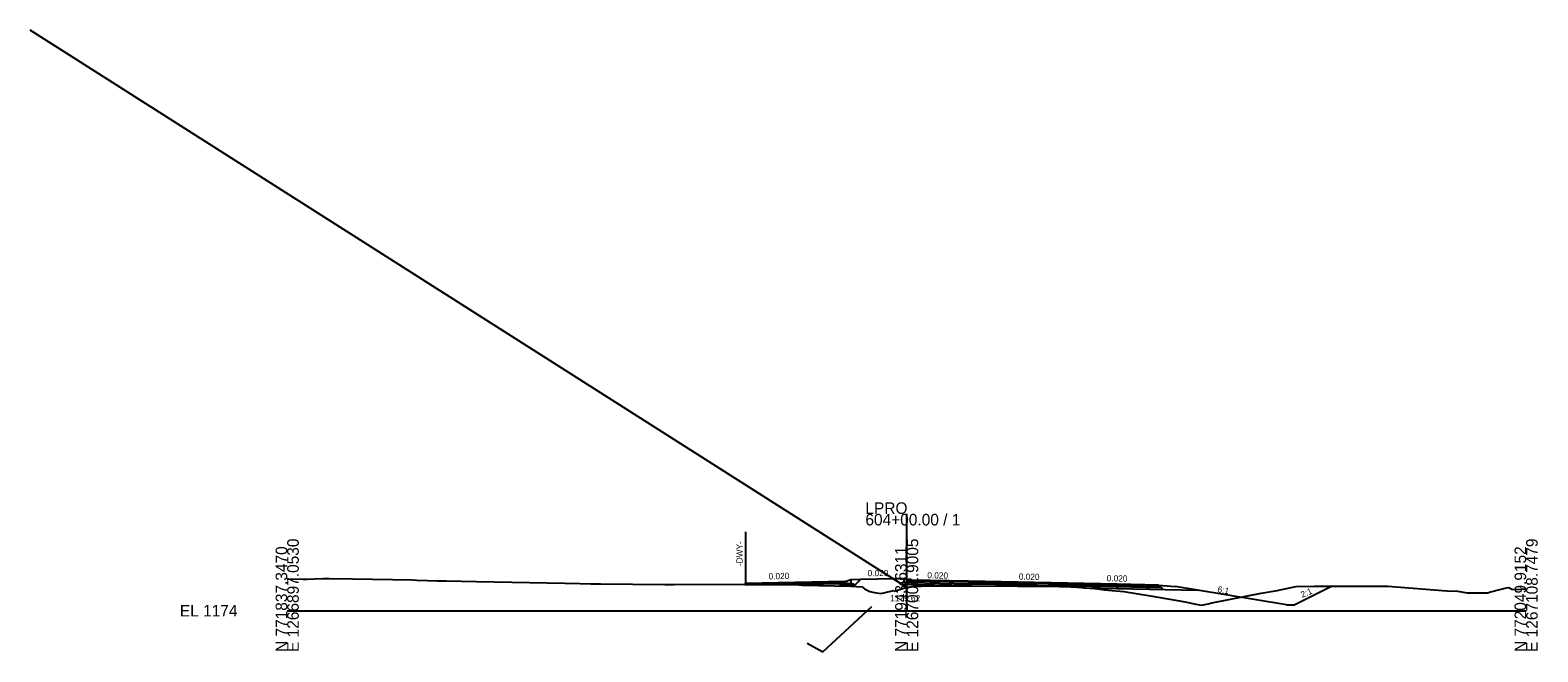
# Model space of a CAD drawing. Extents: x -3833 to 1267678, y -522 to 773248.
# Drawn here: x 937.8 to 1302.8, y 4990 to 5140.7 of the extents above; entities that cross this region are included whole.
import ezdxf

# ---------------------------------------------------------------- set-up
doc = ezdxf.new("R2010")
doc.units = 0
for name, color, linetype in [('Exist Cross Section Cell', 7, 'Continuous'), ('Exist XS Center Line Elevation Label', 7, 'Continuous'), ('Exist XS Ground Line', 7, 'Continuous'), ('Prop CMT DNC', 7, 'Continuous'), ('Prop CMT Pvmt Course 1', 7, 'Continuous'), ('Prop CMT Pvmt Course 2', 7, 'Continuous'), ('Prop CMT Pvmt Course 3', 7, 'Continuous'), ('Prop CMT Pvmt Course 4', 7, 'Continuous'), ('Prop CMT Shld Paved Course 1', 7, 'Continuous'), ('Prop CMT Shld Paved Course 2', 7, 'Continuous'), ('Prop CMT Shld Paved Course 4', 7, 'Continuous'), ('Prop CMT Slope Grass', 7, 'Continuous'), ('Prop CMT Subgrade Earthwork', 7, 'Continuous'), ('Prop Conc Curb and Gutter', 7, 'Continuous'), ('Prop Conc Island Cover', 7, 'Continuous'), ('Prop Corridor Mesh Bottom', 7, 'Continuous'), ('Prop XS Ditch Slope Text', 7, 'Continuous'), ('Prop XS Finish Grade', 7, 'Continuous'), ('Prop XS SE Text', 7, 'Continuous'), ('Prop XS Shear Point Element', 7, 'Continuous'), ('Prop XS Shear Point Label', 7, 'Continuous'), ('Scratch_Level_1', 7, 'Continuous'), ('Scratch_Level_5', 7, 'Continuous')]:
    doc.layers.add(name, color=color, linetype=linetype)

msp = doc.modelspace()

# ---------------------------------------------------------------- linework, layer by layer
at = {"layer": 'Exist Cross Section Cell'}
for p, q in [((1150, 5000), (1150, 5023.46)), ((1000, 5000), (1150, 5000)), ((1150, 5000), (1300, 5000))]:
    msp.add_line(p, q, dxfattribs=at)
at = {"layer": 'Exist XS Ground Line'}
for p, q in [((1000, 5007.74), (1003.75, 5007.64)), ((1003.75, 5007.64), (1004.71, 5007.66)), ((1004.71, 5007.66), (1006.59, 5007.7)), ((1006.59, 5007.7), (1008.72, 5007.77)), ((1008.72, 5007.77), (1010.14, 5007.82)), ((1010.14, 5007.82), (1015.79, 5007.73)), ((1015.79, 5007.73), (1030.31, 5007.48)), ((1030.31, 5007.48), (1031.37, 5007.43)), ((1031.37, 5007.43), (1034, 5007.34)), ((1034, 5007.34), (1036.29, 5007.26)), ((1036.29, 5007.26), (1038.5, 5007.2)), ((1038.5, 5007.2), (1045.86, 5007.04)), ((1045.86, 5007.04), (1067.25, 5006.66)), ((1067.25, 5006.66), (1070.89, 5006.57)), ((1070.89, 5006.57), (1073.51, 5006.54)), ((1073.51, 5006.54), (1075.9, 5006.51)), ((1075.9, 5006.51), (1091.41, 5006.37)), ((1091.41, 5006.37), (1092.62, 5006.36)), ((1092.62, 5006.36), (1093.73, 5006.35)), ((1093.73, 5006.35), (1109.86, 5006.4)), ((1109.86, 5006.4), (1110.85, 5006.39)), ((1110.85, 5006.39), (1111.66, 5006.39)), ((1111.66, 5006.39), (1112.36, 5006.38)), ((1112.36, 5006.38), (1123.85, 5006.24)), ((1123.85, 5006.24), (1124.71, 5006.22)), ((1124.71, 5006.22), (1136.51, 5005.92)), ((1136.51, 5005.92), (1139.26, 5005.78)), ((1139.26, 5005.78), (1139.8, 5005.29)), ((1146.97, 5004.7), (1149.35, 5005.48)), ((1149.35, 5005.48), (1150, 5005.62)), ((1150, 5005.62), (1150.37, 5005.69)), ((1150.37, 5005.69), (1151.55, 5005.93)), ((1151.55, 5005.93), (1153.6, 5005.98)), ((1153.6, 5005.98), (1160.64, 5006.02)), ((1160.64, 5006.02), (1165.83, 5006.05)), ((1165.83, 5006.05), (1176.95, 5005.96)), ((1176.95, 5005.96), (1178.3, 5005.94)), ((1178.3, 5005.94), (1181.63, 5005.91)), ((1181.63, 5005.91), (1187.02, 5005.84)), ((1187.02, 5005.84), (1189.65, 5005.81)), ((1189.65, 5005.81), (1190.26, 5005.76)), ((1190.26, 5005.76), (1195.46, 5005.35)), ((1239.71, 5004.9), (1244.22, 5005.84)), ((1244.22, 5005.84), (1248.79, 5005.92)), ((1248.79, 5005.92), (1266.54, 5005.92)), ((1266.54, 5005.92), (1280.84, 5004.82)), ((1293.94, 5005.2), (1295.28, 5005.55)), ((1295.28, 5005.55), (1295.83, 5005.66)), ((1295.83, 5005.66), (1296.56, 5005.18)), ((1139.8, 5005.29), (1141.09, 5004.67)), ((1141.09, 5004.67), (1142.22, 5004.43)), ((1142.22, 5004.43), (1143.71, 5004.19)), ((1143.71, 5004.19), (1146.2, 5004.73)), ((1146.2, 5004.73), (1146.95, 5004.86)), ((1146.95, 5004.86), (1146.97, 5004.7)), ((1195.46, 5005.35), (1196.19, 5005.27)), ((1196.19, 5005.27), (1197.9, 5005.09)), ((1197.9, 5005.09), (1201.6, 5004.75)), ((1201.6, 5004.75), (1202.62, 5004.62)), ((1202.62, 5004.62), (1209.04, 5003.6)), ((1209.04, 5003.6), (1217.43, 5002.17)), ((1217.43, 5002.17), (1218.17, 5002)), ((1218.17, 5002), (1220.01, 5001.62)), ((1222.98, 5001.68), (1223.92, 5001.93)), ((1223.92, 5001.93), (1235.82, 5004.28)), ((1235.82, 5004.28), (1239.71, 5004.9)), ((1280.84, 5004.82), (1283.36, 5004.7)), ((1283.36, 5004.7), (1285.74, 5004.34)), ((1285.74, 5004.34), (1286.6, 5004.34)), ((1286.6, 5004.34), (1290.73, 5004.33)), ((1290.73, 5004.33), (1291.16, 5004.52)), ((1291.16, 5004.52), (1293.94, 5005.2)), ((1296.56, 5005.18), (1297.34, 5005.12)), ((1297.34, 5005.12), (1300, 5005.28)), ((1220.01, 5001.62), (1221.39, 5001.33)), ((1221.39, 5001.33), (1222.98, 5001.68))]:
    msp.add_line(p, q, dxfattribs=at)
at = {"layer": 'Prop CMT Pvmt Course 1'}
for p, q in [((1111, 5006.66), (1135, 5007.14)), ((1111, 5006.41), (1111, 5006.66)), ((1111, 5006.66), (1111, 5006.66)), ((1135, 5007.14), (1135, 5007.14)), ((1135, 5007.14), (1135, 5007.14)), ((1135, 5007.14), (1135, 5006.89)), ((1135, 5006.89), (1135, 5006.89)), ((1201, 5006.42), (1165, 5007.14)), ((1165, 5007.14), (1165, 5007.14)), ((1165, 5007.14), (1165, 5007.14)), ((1165, 5007.14), (1165, 5006.89)), ((1165, 5006.89), (1165, 5006.89)), ((1201, 5006.42), (1195, 5006.54)), ((1195, 5006.29), (1195, 5006.54)), ((1195, 5006.54), (1195, 5006.54)), ((1195, 5006.54), (1195, 5006.54)), ((1195, 5006.54), (1201, 5006.42)), ((1195, 5006.29), (1201, 5006.17)), ((1201, 5006.17), (1201, 5006.42))]:
    msp.add_line(p, q, dxfattribs=at)
at = {"layer": 'Prop CMT Pvmt Course 2'}
for p, q in [((1135, 5006.89), (1135, 5006.89)), ((1135, 5006.89), (1135, 5006.56)), ((1135, 5006.56), (1135, 5006.55)), ((1150, 5007.19), (1150, 5007.19)), ((1150, 5007.19), (1150, 5007.19)), ((1150, 5006.86), (1150, 5006.86)), ((1150, 5006.86), (1150, 5006.86)), ((1165, 5006.89), (1150.94, 5007.17)), ((1150.94, 5006.84), (1165, 5006.55)), ((1165, 5006.89), (1165, 5006.89)), ((1165, 5006.55), (1165, 5006.55)), ((1195, 5005.96), (1201, 5005.84))]:
    msp.add_line(p, q, dxfattribs=at)
at = {"layer": 'Prop CMT Pvmt Course 3'}
for p, q in [((1135, 5006.55), (1137.01, 5006.6)), ((1135, 5006.55), (1135, 5006.55)), ((1137.01, 5006.6), (1137.01, 5006.6)), ((1137.01, 5006.6), (1137.01, 5006.6)), ((1137.01, 5006.6), (1137.46, 5006.15)), ((1137.3, 5006.31), (1137.3, 5006.31)), ((1148.48, 5006.43), (1148.93, 5006.88)), ((1148.93, 5006.88), (1149.43, 5006.87))]:
    msp.add_line(p, q, dxfattribs=at)
at = {"layer": 'Prop CMT Pvmt Course 4'}
for p, q in [((1134, 5005.98), (1134, 5007.12)), ((1137.46, 5006.15), (1134, 5006.08)), ((1135, 5006.56), (1135, 5006.56)), ((1135, 5006.56), (1135, 5006.55)), ((1138.29, 5005.83), (1138.29, 5005.83)), ((1150, 5006.86), (1150, 5006.86)), ((1150, 5006.86), (1150, 5006.86)), ((1165, 5006.55), (1165, 5006.55)), ((1165, 5006.55), (1165, 5006.55)), ((1165, 5006.55), (1165, 5006.05)), ((1195, 5005.96), (1195, 5005.5)), ((1201, 5005.84), (1195, 5005.96)), ((1195, 5005.5), (1201, 5005.38))]:
    msp.add_line(p, q, dxfattribs=at)
at = {"layer": 'Prop CMT Shld Paved Course 1'}
for p, q in [((1135, 5007.14), (1135, 5007.14)), ((1135, 5007.14), (1135, 5006.89)), ((1150, 5007.44), (1150, 5007.44)), ((1150, 5007.44), (1150, 5007.44)), ((1150, 5007.19), (1150, 5007.19)), ((1150, 5007.19), (1150, 5007.19)), ((1165, 5007.14), (1150.94, 5007.42)), ((1165, 5006.89), (1165, 5007.14)), ((1165, 5007.14), (1165, 5007.14)), ((1201, 5006.42), (1201, 5006.17)), ((1211, 5006.22), (1201, 5006.42)), ((1201, 5006.17), (1211.26, 5005.96)), ((1211.26, 5005.96), (1211, 5006.22))]:
    msp.add_line(p, q, dxfattribs=at)
at = {"layer": 'Prop CMT Shld Paved Course 2'}
for p, q in [((1111, 5006.41), (1111.66, 5006.42)), ((1111, 5006.39), (1111, 5006.41)), ((1111.66, 5006.42), (1112.36, 5006.44)), ((1111.66, 5006.42), (1111.66, 5006.42)), ((1111.66, 5006.39), (1111.66, 5006.39)), ((1112.36, 5006.44), (1123.85, 5006.66)), ((1112.36, 5006.44), (1112.36, 5006.44)), ((1112.36, 5006.38), (1112.36, 5006.38)), ((1123.85, 5006.33), (1121.08, 5006.28)), ((1121.08, 5006.28), (1121.08, 5006.28)), ((1123.85, 5006.66), (1124.71, 5006.68)), ((1123.85, 5006.66), (1123.85, 5006.66)), ((1124.71, 5006.35), (1123.85, 5006.33)), ((1123.85, 5006.33), (1123.85, 5006.33)), ((1124.71, 5006.68), (1135, 5006.89)), ((1124.71, 5006.68), (1124.71, 5006.68)), ((1135, 5006.55), (1124.71, 5006.35)), ((1124.71, 5006.35), (1124.71, 5006.35)), ((1135, 5006.89), (1135, 5006.89)), ((1135, 5006.89), (1135, 5006.89)), ((1135, 5006.89), (1135, 5006.55)), ((1135, 5006.55), (1135, 5006.55)), ((1165.83, 5006.87), (1165, 5006.89)), ((1165, 5006.89), (1165, 5006.89)), ((1165, 5006.89), (1165, 5006.89)), ((1165, 5006.89), (1165, 5006.55)), ((1165, 5006.55), (1165, 5006.55)), ((1165, 5006.55), (1165.83, 5006.54)), ((1165.98, 5006.87), (1165.83, 5006.87)), ((1165.83, 5006.54), (1176.95, 5006.32)), ((1176.95, 5006.65), (1165.98, 5006.87)), ((1165.98, 5006.87), (1165.98, 5006.87)), ((1165.98, 5006.54), (1165.98, 5006.54)), ((1178.3, 5006.62), (1176.95, 5006.65)), ((1176.95, 5006.65), (1176.95, 5006.65)), ((1176.95, 5006.32), (1176.95, 5006.32)), ((1176.95, 5006.32), (1178.3, 5006.29)), ((1181.63, 5006.56), (1178.3, 5006.62)), ((1178.3, 5006.29), (1181.63, 5006.22)), ((1187.02, 5006.45), (1181.63, 5006.56)), ((1181.63, 5006.56), (1181.63, 5006.56)), ((1181.63, 5006.22), (1181.63, 5006.22)), ((1181.63, 5006.22), (1187.02, 5006.11)), ((1189.65, 5006.39), (1187.02, 5006.45)), ((1187.02, 5006.45), (1187.02, 5006.45)), ((1187.02, 5006.11), (1187.02, 5006.11)), ((1187.02, 5006.11), (1189.65, 5006.06)), ((1190.26, 5006.38), (1189.65, 5006.39)), ((1189.65, 5006.06), (1190.26, 5006.05)), ((1195, 5006.29), (1190.26, 5006.38)), ((1190.26, 5006.38), (1190.26, 5006.38)), ((1190.26, 5006.05), (1190.26, 5006.05)), ((1190.26, 5006.05), (1195, 5005.95)), ((1195, 5005.95), (1195, 5006.29)), ((1195, 5006.29), (1195, 5006.29)), ((1201, 5006.17), (1201, 5005.84)), ((1201, 5005.84), (1211.59, 5005.63)), ((1211.59, 5005.63), (1211.26, 5005.96))]:
    msp.add_line(p, q, dxfattribs=at)
at = {"layer": 'Prop CMT Shld Paved Course 4'}
for p, q in [((1201, 5005.84), (1201, 5005.38)), ((1211.09, 5005.64), (1201, 5005.84)), ((1212.06, 5005.16), (1211.59, 5005.63))]:
    msp.add_line(p, q, dxfattribs=at)
at = {"layer": 'Prop CMT Slope Grass'}
for p, q in [((1136.51, 5007.57), (1138.94, 5007.62)), ((1147.11, 5007.8), (1149.43, 5007.85)), ((1211, 5006.22), (1215, 5005.9)), ((1220.43, 5004.99), (1215, 5005.9))]:
    msp.add_line(p, q, dxfattribs=at)
at = {"layer": 'Prop CMT Subgrade Earthwork'}
for p, q in [((1134, 5006.08), (1137.46, 5006.15)), ((1134, 5006.08), (1134, 5005.98)), ((1138.94, 5007.62), (1137.46, 5006.15)), ((1147.11, 5007.8), (1148.48, 5006.43)), ((1148.48, 5006.43), (1165, 5006.1)), ((1165, 5006.05), (1165, 5006.1)), ((1193.09, 5005.53), (1220.43, 5004.99))]:
    msp.add_line(p, q, dxfattribs=at)
at = {"layer": 'Prop Conc Curb and Gutter'}
for p, q in [((1135, 5007.14), (1135.75, 5007.15)), ((1135, 5006.55), (1135, 5007.14)), ((1135, 5007.14), (1135, 5007.14)), ((1136.51, 5006.59), (1135, 5006.55)), ((1135.75, 5007.32), (1136.51, 5007.57)), ((1135.75, 5007.15), (1135.75, 5007.32)), ((1135.75, 5007.32), (1135.75, 5007.32)), ((1135.75, 5007.15), (1135.75, 5007.15)), ((1136.51, 5007.57), (1136.51, 5007.57)), ((1136.51, 5007.57), (1136.51, 5007.57)), ((1136.51, 5007.57), (1136.51, 5006.59)), ((1136.51, 5006.59), (1136.51, 5006.59)), ((1149.43, 5006.87), (1149.43, 5007.85)), ((1149.43, 5007.85), (1149.71, 5007.76)), ((1150.94, 5006.84), (1149.43, 5006.87)), ((1149.71, 5007.76), (1150.19, 5007.6)), ((1150.19, 5007.6), (1150.19, 5007.56)), ((1150.19, 5007.56), (1150.19, 5007.43)), ((1150.19, 5007.43), (1150.33, 5007.43)), ((1150.33, 5007.43), (1150.94, 5007.42)), ((1150.94, 5007.42), (1150.94, 5007.42)), ((1150.94, 5007.42), (1150.94, 5006.84))]:
    msp.add_line(p, q, dxfattribs=at)
at = {"layer": 'Prop Conc Island Cover'}
for p, q in [((1136.51, 5007.57), (1136.51, 5007.57)), ((1136.51, 5007.32), (1136.51, 5007.32))]:
    msp.add_line(p, q, dxfattribs=at)
at = {"layer": 'Prop Corridor Mesh Bottom'}
for p, q in [((1111, 5006.66), (1111, 5006.41)), ((1135, 5007.14), (1135, 5006.89))]:
    msp.add_line(p, q, dxfattribs=at)
at = {"layer": 'Prop XS Finish Grade'}
for p, q in [((1136.51, 5007.57), (1136.51, 5007.57)), ((1138.94, 5007.62), (1147.11, 5007.8)), ((1215, 5005.9), (1215, 5005.9)), ((1253.05, 5005.92), (1244, 5001.4)), ((1242, 5001.4), (1220.43, 5004.99)), ((1242, 5001.4), (1244, 5001.4))]:
    msp.add_line(p, q, dxfattribs=at)
at = {"layer": 'Prop XS Shear Point Element'}
msp.add_line((1111, 5019.14), (1111, 5006.39), dxfattribs=at)
at = {"layer": 'Scratch_Level_1'}
msp.add_line((1150, 5005.62), (937.75, 5140.67), dxfattribs=at)
at = {"layer": 'Scratch_Level_5'}
for p, q in [((1129.67, 4990.03), (1141.53, 5001.05)), ((1125.89, 4992.13), (1129.67, 4990.03))]:
    msp.add_line(p, q, dxfattribs=at)

# ---------------------------------------------------------------- texts
at = {"layer": 'Exist Cross Section Cell'}
for s, p in [('LPRO', (1140, 5023.46)), ('604+00.00 / 1', (1140, 5020.66)), ('EL 1174', (974, 4998.6))]:
    msp.add_text(s, height=2.8, dxfattribs=at).set_placement(p)
for s, p in [('E 1266897.0530', (1002.8, 4990)), ('E 1267002.9005', (1152.8, 4990)), ('E 1267108.7479', (1302.8, 4990)), ('N 771837.3470', (1000, 4990)), ('N 771943.6311', (1150, 4990)), ('N 772049.9152', (1300, 4990))]:
    msp.add_text(s, height=2.8, rotation=90, dxfattribs=at).set_placement(p)
at = {"layer": 'Exist XS Center Line Elevation Label'}
msp.add_text('1179.62', height=1.5, dxfattribs=at).set_placement((1146.01, 5002.28))
at = {"layer": 'Prop CMT DNC'}
for p in [(1101, 5006.46), (1111, 5006.66), (1111, 5006.66), (1135, 5007.14), (1135, 5007.14), (1135.75, 5007.15), (1150, 5007.44), (1150.19, 5007.43), (1165, 5007.14), (1165, 5007.14), (1201, 5006.42), (1201, 5006.42), (1211, 5006.22), (1244.93, 5005.86)]:
    msp.add_text('X', height=0.00025, dxfattribs=at).set_placement(p)
at = {"layer": 'Prop XS Ditch Slope Text'}
for s, rotation, p in [('6:1', 349.0214, (1225.19, 5004.51)), ('2:1', 22.8609, (1245.79, 5003.11))]:
    msp.add_text(s, height=1.5, rotation=rotation, dxfattribs=at).set_placement(p)
at = {"layer": 'Prop XS SE Text'}
for rotation, p in [(1.397, (1116.58, 5007.58)), (0.2693, (1140.55, 5008.36)), (358.8542, (1154.99, 5007.86)), (358.8542, (1177.14, 5007.54)), (358.8542, (1198.43, 5007.14))]:
    msp.add_text('0.020', height=1.5, rotation=rotation, dxfattribs=at).set_placement(p)
at = {"layer": 'Prop XS Shear Point Label'}
msp.add_text('-DWY-', height=1.5, rotation=90, dxfattribs=at).set_placement((1110.27, 5010.82))

doc.saveas('drawing.dxf')
